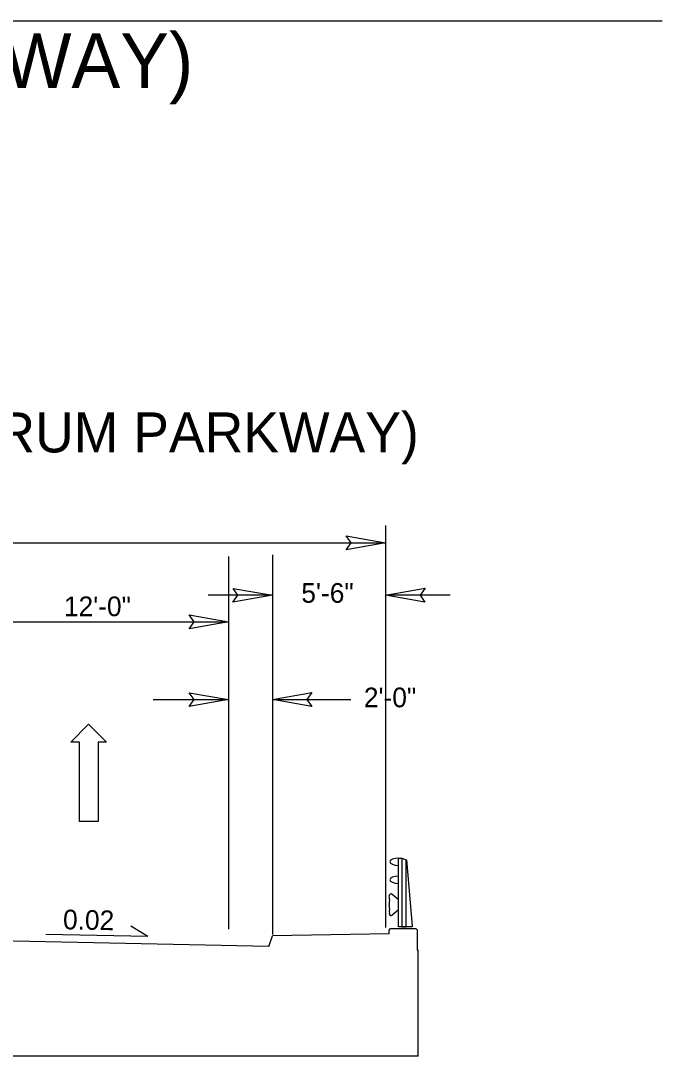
# Model space of a CAD drawing. Extents: x 1904401 to 1905163, y 193929 to 194736.
# Drawn here: x 1904591.41 to 1904620.77, y 194429.01 to 194476.4 of the extents above; entities that cross this region are included whole.
import ezdxf

# ---------------------------------------------------------------- set-up
doc = ezdxf.new("R2010")
doc.units = 0
for name, color, linetype in [('Old_Level_1', 7, 'Continuous'), ('Prop Dimension', 7, 'Continuous'), ('Prop Dimension Text', 7, 'Continuous'), ('Prop Lane Arrow CELL', 7, 'Continuous'), ('Prop Terminator CELL', 7, 'Continuous'), ('Typical Pavement Slope CELL', 7, 'Continuous'), ('Typical Pavement Slope Information CELL', 7, 'Continuous'), ('Typical Sidewalk and Rail CELL', 7, 'Continuous'), ('Typical Text Centerline CELL', 7, 'Continuous')]:
    doc.layers.add(name, color=color, linetype=linetype)

msp = doc.modelspace()

# ---------------------------------------------------------------- linework, layer by layer
at = {"layer": 'Old_Level_1'}
msp.add_line((1904539.486, 194476.403), (1904620.766, 194476.403), dxfattribs=at)
at = {"layer": 'Prop Dimension'}
for p, q in [((1904608.102, 194453.307), (1904608.102, 194434.9)), ((1904552.242, 194452.516), (1904608.102, 194452.516)), ((1904600.922, 194451.878), (1904600.922, 194434.827)), ((1904602.922, 194451.957), (1904602.922, 194434.589)), ((1904602.922, 194450.111), (1904599.982, 194450.111)), ((1904611.058, 194450.111), (1904608.102, 194450.111)), ((1904600.922, 194449.54), (1904600.922, 194434.915)), ((1904588.922, 194448.899), (1904600.922, 194448.899)), ((1904597.468, 194445.335), (1904600.922, 194445.335)), ((1904602.922, 194445.335), (1904606.515, 194445.335))]:
    msp.add_line(p, q, dxfattribs=at)
at = {"layer": 'Prop Lane Arrow CELL'}
for p, q in [((1904593.704, 194443.392), (1904594.508, 194444.209)), ((1904594.508, 194444.209), (1904595.338, 194443.392)), ((1904594.093, 194443.392), (1904593.704, 194443.392)), ((1904594.093, 194439.761), (1904594.093, 194443.392)), ((1904595.338, 194443.392), (1904594.949, 194443.392)), ((1904594.949, 194443.392), (1904594.949, 194439.761)), ((1904594.949, 194439.761), (1904594.093, 194439.761))]:
    msp.add_line(p, q, dxfattribs=at)
at = {"layer": 'Prop Terminator CELL'}
for points in [[(1904606.302, 194452.826), (1904608.102, 194452.516), (1904606.292, 194452.196), (1904606.522, 194452.516)], [(1904601.122, 194450.421), (1904602.922, 194450.111), (1904601.112, 194449.791), (1904601.342, 194450.111)], [(1904609.902, 194449.801), (1904608.102, 194450.111), (1904609.912, 194450.431), (1904609.682, 194450.111)], [(1904599.122, 194449.209), (1904600.922, 194448.899), (1904599.112, 194448.579), (1904599.342, 194448.899)], [(1904599.122, 194445.645), (1904600.922, 194445.335), (1904599.112, 194445.015), (1904599.342, 194445.335)], [(1904604.722, 194445.025), (1904602.922, 194445.335), (1904604.732, 194445.655), (1904604.502, 194445.335)]]:
    msp.add_lwpolyline(points, close=True, dxfattribs=at)
at = {"layer": 'Typical Pavement Slope CELL'}
msp.add_line((1904602.762, 194434.042), (1904579.661, 194434.504), dxfattribs=at)
at = {"layer": 'Typical Pavement Slope Information CELL'}
for q in [(1904596.438, 194434.971), (1904592.561, 194434.591)]:
    msp.add_line((1904597.221, 194434.497), q, dxfattribs=at)
at = {"layer": 'Typical Sidewalk and Rail CELL'}
for p, q in [((1904608.283, 194436.264), (1904608.272, 194436.349)), ((1904608.684, 194436.193), (1904608.407, 194436.421)), ((1904608.272, 194435.985), (1904608.272, 194435.945)), ((1904608.272, 194435.905), (1904608.272, 194435.945)), ((1904608.283, 194435.627), (1904608.272, 194435.542)), ((1904608.684, 194435.698), (1904608.407, 194435.469)), ((1904608.261, 194434.79), (1904608.334, 194434.863)), ((1904608.261, 194434.613), (1904608.261, 194434.79)), ((1904608.334, 194434.863), (1904609.488, 194434.863)), ((1904608.519, 194434.855), (1904608.602, 194434.855)), ((1904609.21, 194434.855), (1904609.272, 194434.855)), ((1904609.552, 194434.798), (1904609.488, 194434.863)), ((1904609.552, 194434.798), (1904609.552, 194433.869)), ((1904602.762, 194434.042), (1904602.922, 194434.524)), ((1904608.261, 194434.613), (1904602.922, 194434.524)), ((1904609.594, 194433.869), (1904609.552, 194433.869)), ((1904609.594, 194429.012), (1904609.594, 194433.869)), ((1904550.75, 194429.038), (1904609.594, 194429.038))]:
    msp.add_line(p, q, dxfattribs=at)
msp.add_lwpolyline([(1904608.695, 194438.08), (1904608.839, 194438.08), (1904609.046, 194437.997), (1904609.066, 194437.997), (1904609.313, 194434.966), (1904609.313, 194434.935), (1904608.695, 194434.935), (1904608.695, 194438.08), (1904608.839, 194438.08), (1904608.839, 194434.935), (1904609.046, 194434.935), (1904609.046, 194437.997)], dxfattribs=at)
for centre, radius, start, end in [((1904608.354, 194436.358), 0.0824, 50.5568, 186.0672), ((1904608.007, 194436.074), 0.279, 341.4179, 354.5265), ((1904608.526, 194436.164), 0.247, 173.18, 190.7949), ((1904608.054, 194436.237), 0.23, 349.2013, 6.82), ((1904608.057, 194436.075), 0.23, 353.18, 10.7987), ((1904608.007, 194435.816), 0.279, 5.4735, 18.5821), ((1904608.526, 194435.726), 0.247, 169.2051, 186.82), ((1904608.054, 194435.654), 0.23, 353.18, 10.7987), ((1904608.057, 194435.816), 0.23, 349.2013, 6.82), ((1904608.354, 194435.533), 0.0824, 173.9328, 309.4432)]:
    msp.add_arc(centre, radius, start, end, dxfattribs=at)
for centre, start_param, end_param in [((1904608.695, 194437.915), 4.712389, 6.283185), ((1904608.695, 194437.915), 0, 1.570796), ((1904608.695, 194437.09), 4.712389, 6.283185), ((1904608.695, 194437.09), 0, 1.570796)]:
    msp.add_ellipse(centre, major_axis=(-0.392, 0), ratio=0.42124, start_param=start_param, end_param=end_param, dxfattribs=at)

# ---------------------------------------------------------------- texts
at = {"layer": 'Prop Dimension'}
msp.add_text('2\'-0"', height=0.9, dxfattribs=at).set_placement((1904607.11, 194444.984))
at = {"layer": 'Prop Dimension Text'}
for s, height, p in [('-L- (FORUM PARKWAY) ', 2.5, (1904562.16, 194473.33)), ('12\'-0"', 0.9, (1904593.384, 194449.153))]:
    msp.add_text(s, height=height, dxfattribs=at).set_placement(p)
msp.add_text('5\'-6"', height=0.9, rotation=360, dxfattribs=at).set_placement((1904604.248, 194449.767))
at = {"layer": 'Typical Pavement Slope Information CELL'}
msp.add_text('0.02', height=0.9, rotation=358.8543, dxfattribs=at).set_placement((1904593.334, 194434.826))
at = {"layer": 'Typical Text Centerline CELL'}
msp.add_text('-L- (FORUM PARKWAY)', height=1.83231, rotation=0, dxfattribs=at).set_placement((1904582.399, 194456.646))

doc.saveas('drawing.dxf')
